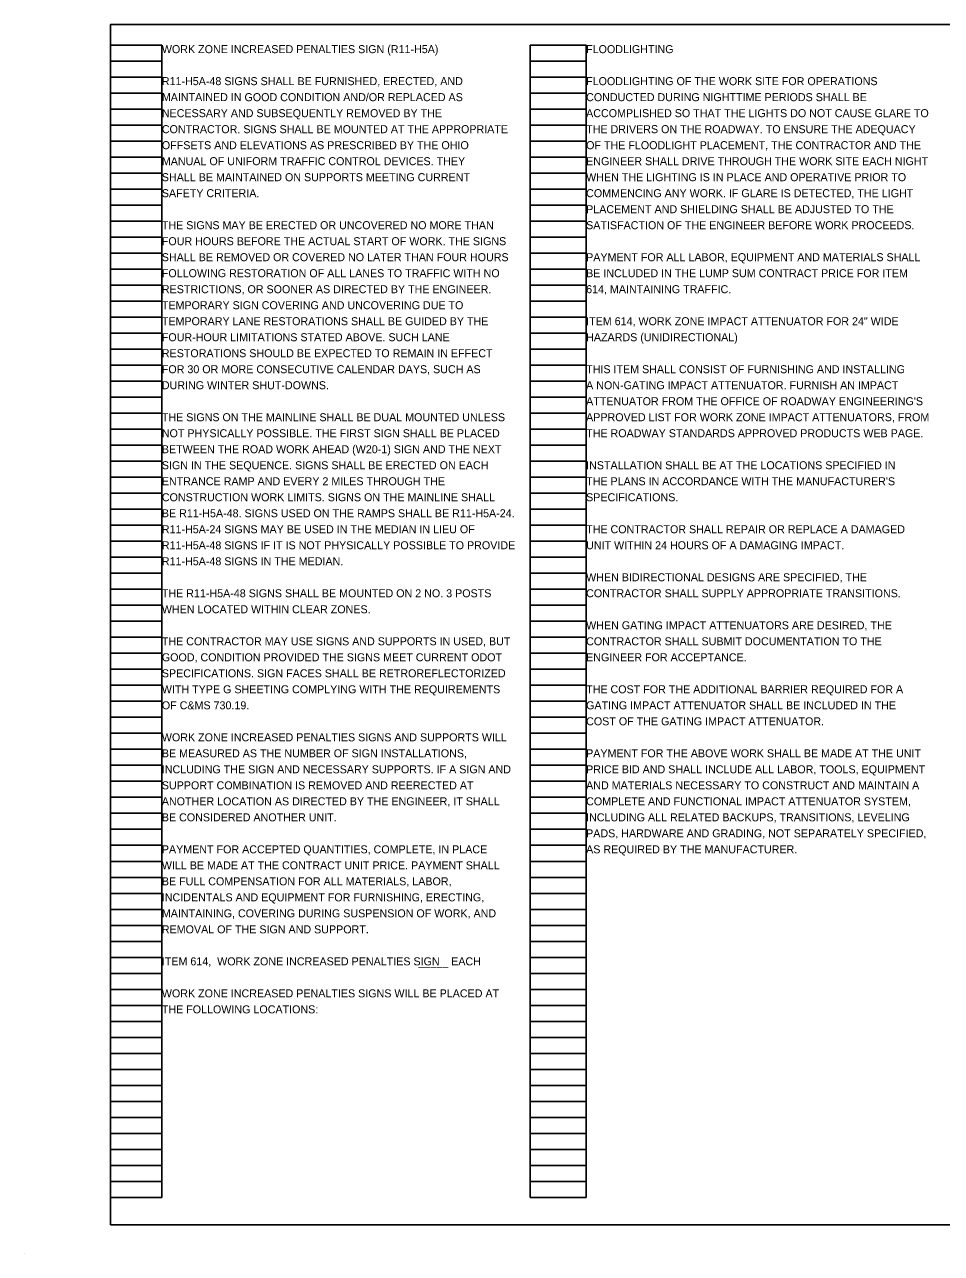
# Model space of a CAD drawing. Extents: x -34 to 2132911, y 0 to 658646.
# Drawn here: x 34 to 50.03, y 0 to 21.5 of the extents above; entities that cross this region are included whole.
import ezdxf

# ---------------------------------------------------------------- set-up
doc = ezdxf.new("R2010")
doc.units = 0
for name, color, linetype in [('SC_Scratch1', 7, 'Continuous'), ('SH_Data', 7, 'Continuous'), ('SH_Text', 7, 'Continuous')]:
    doc.layers.add(name, color=color, linetype=linetype)

msp = doc.modelspace()

# ---------------------------------------------------------------- linework, layer by layer
at = {"layer": 'SC_Scratch1'}
msp.add_lwpolyline([(35.5, 0.5), (66, 0.5), (66, 21.5), (35.5, 21.5)], close=True, dxfattribs=at)
at = {"layer": 'SH_Data'}
for p, q in [((35.5, 0.98), (35.5, 21.14)), ((35.5, 21.14), (36.4, 21.14)), ((36.4, 0.98), (36.4, 21.14)), ((42.84, 0.98), (42.84, 21.14)), ((42.84, 21.14), (43.82, 21.14)), ((43.82, 0.98), (43.82, 21.14)), ((35.5, 20.86), (36.4, 20.86)), ((42.84, 20.86), (43.82, 20.86)), ((35.5, 20.58), (36.4, 20.58)), ((42.84, 20.58), (43.82, 20.58)), ((35.5, 20.3), (36.4, 20.3)), ((42.84, 20.3), (43.82, 20.3)), ((35.5, 20.02), (36.4, 20.02)), ((42.84, 20.02), (43.82, 20.02)), ((35.5, 19.74), (36.4, 19.74)), ((42.84, 19.74), (43.82, 19.74)), ((35.5, 19.46), (36.4, 19.46)), ((42.84, 19.46), (43.82, 19.46)), ((35.5, 19.18), (36.4, 19.18)), ((42.84, 19.18), (43.82, 19.18)), ((35.5, 18.9), (36.4, 18.9)), ((42.84, 18.9), (43.82, 18.9)), ((35.5, 18.62), (36.4, 18.62)), ((42.84, 18.62), (43.82, 18.62)), ((35.5, 18.34), (36.4, 18.34)), ((42.84, 18.34), (43.82, 18.34)), ((35.5, 18.06), (36.4, 18.06)), ((42.84, 18.06), (43.82, 18.06)), ((35.5, 17.78), (36.4, 17.78)), ((42.84, 17.78), (43.82, 17.78)), ((35.5, 17.5), (36.4, 17.5)), ((42.84, 17.5), (43.82, 17.5)), ((35.5, 17.22), (36.4, 17.22)), ((42.84, 17.22), (43.82, 17.22)), ((35.5, 16.94), (36.4, 16.94)), ((42.84, 16.94), (43.82, 16.94)), ((35.5, 16.66), (36.4, 16.66)), ((42.84, 16.66), (43.82, 16.66)), ((35.5, 16.38), (36.4, 16.38)), ((42.84, 16.38), (43.82, 16.38)), ((35.5, 16.1), (36.4, 16.1)), ((42.84, 16.1), (43.82, 16.1)), ((35.5, 15.82), (36.4, 15.82)), ((42.84, 15.82), (43.82, 15.82)), ((35.5, 15.54), (36.4, 15.54)), ((42.84, 15.54), (43.82, 15.54)), ((35.5, 15.26), (36.4, 15.26)), ((42.84, 15.26), (43.82, 15.26)), ((35.5, 14.98), (36.4, 14.98)), ((42.84, 14.98), (43.82, 14.98)), ((35.5, 14.7), (36.4, 14.7)), ((42.84, 14.7), (43.82, 14.7)), ((35.5, 14.42), (36.4, 14.42)), ((42.84, 14.42), (43.82, 14.42)), ((35.5, 14.14), (36.4, 14.14)), ((42.84, 14.14), (43.82, 14.14)), ((35.5, 13.86), (36.4, 13.86)), ((42.84, 13.86), (43.82, 13.86)), ((35.5, 13.58), (36.4, 13.58)), ((42.84, 13.58), (43.82, 13.58)), ((35.5, 13.3), (36.4, 13.3)), ((42.84, 13.3), (43.82, 13.3)), ((35.5, 13.02), (36.4, 13.02)), ((42.84, 13.02), (43.82, 13.02)), ((35.5, 12.74), (36.4, 12.74)), ((42.84, 12.74), (43.82, 12.74)), ((35.5, 12.46), (36.4, 12.46)), ((42.84, 12.46), (43.82, 12.46)), ((35.5, 12.18), (36.4, 12.18)), ((42.84, 12.18), (43.82, 12.18)), ((35.5, 11.9), (36.4, 11.9)), ((42.84, 11.9), (43.82, 11.9)), ((35.5, 11.62), (36.4, 11.62)), ((42.84, 11.62), (43.82, 11.62)), ((35.5, 11.34), (36.4, 11.34)), ((42.84, 11.34), (43.82, 11.34)), ((35.5, 11.06), (36.4, 11.06)), ((42.84, 11.06), (43.82, 11.06)), ((35.5, 10.78), (36.4, 10.78)), ((42.84, 10.78), (43.82, 10.78)), ((35.5, 10.5), (36.4, 10.5)), ((42.84, 10.5), (43.82, 10.5)), ((35.5, 10.22), (36.4, 10.22)), ((42.84, 10.22), (43.82, 10.22)), ((35.5, 9.94), (36.4, 9.94)), ((42.84, 9.94), (43.82, 9.94)), ((35.5, 9.66), (36.4, 9.66)), ((42.84, 9.66), (43.82, 9.66)), ((35.5, 9.38), (36.4, 9.38)), ((42.84, 9.38), (43.82, 9.38)), ((35.5, 9.1), (36.4, 9.1)), ((42.84, 9.1), (43.82, 9.1)), ((35.5, 8.82), (36.4, 8.82)), ((42.84, 8.82), (43.82, 8.82)), ((35.5, 8.54), (36.4, 8.54)), ((42.84, 8.54), (43.82, 8.54)), ((35.5, 8.26), (36.4, 8.26)), ((42.84, 8.26), (43.82, 8.26)), ((35.5, 7.98), (36.4, 7.98)), ((42.84, 7.98), (43.82, 7.98)), ((35.5, 7.7), (36.4, 7.7)), ((42.84, 7.7), (43.82, 7.7)), ((35.5, 7.42), (36.4, 7.42)), ((42.84, 7.42), (43.82, 7.42)), ((35.5, 7.14), (36.4, 7.14)), ((42.84, 7.14), (43.82, 7.14)), ((35.5, 6.86), (36.4, 6.86)), ((42.84, 6.86), (43.82, 6.86)), ((35.5, 6.58), (36.4, 6.58)), ((42.84, 6.58), (43.82, 6.58)), ((35.5, 6.3), (36.4, 6.3)), ((42.84, 6.3), (43.82, 6.3)), ((35.5, 6.02), (36.4, 6.02)), ((42.84, 6.02), (43.82, 6.02)), ((35.5, 5.74), (36.4, 5.74)), ((42.84, 5.74), (43.82, 5.74)), ((35.5, 5.46), (36.4, 5.46)), ((42.84, 5.46), (43.82, 5.46)), ((35.5, 5.18), (36.4, 5.18)), ((42.84, 5.18), (43.82, 5.18)), ((35.5, 4.9), (36.4, 4.9)), ((42.84, 4.9), (43.82, 4.9)), ((35.5, 4.62), (36.4, 4.62)), ((42.84, 4.62), (43.82, 4.62)), ((35.5, 4.34), (36.4, 4.34)), ((42.84, 4.34), (43.82, 4.34)), ((35.5, 4.06), (36.4, 4.06)), ((42.84, 4.06), (43.82, 4.06)), ((35.5, 3.78), (36.4, 3.78)), ((42.84, 3.78), (43.82, 3.78)), ((35.5, 3.5), (36.4, 3.5)), ((42.84, 3.5), (43.82, 3.5)), ((35.5, 3.22), (36.4, 3.22)), ((42.84, 3.22), (43.82, 3.22)), ((35.5, 2.94), (36.4, 2.94)), ((42.84, 2.94), (43.82, 2.94)), ((35.5, 2.66), (36.4, 2.66)), ((42.84, 2.66), (43.82, 2.66)), ((35.5, 2.38), (36.4, 2.38)), ((42.84, 2.38), (43.82, 2.38)), ((35.5, 2.1), (36.4, 2.1)), ((42.84, 2.1), (43.82, 2.1)), ((35.5, 1.82), (36.4, 1.82)), ((42.84, 1.82), (43.82, 1.82)), ((35.5, 1.54), (36.4, 1.54)), ((42.84, 1.54), (43.82, 1.54)), ((35.5, 1.26), (36.4, 1.26)), ((42.84, 1.26), (43.82, 1.26)), ((35.5, 0.98), (36.4, 0.98)), ((42.84, 0.98), (43.82, 0.98)), ((34, 0), (34, 0))]:
    msp.add_line(p, q, dxfattribs=at)

# ---------------------------------------------------------------- texts
at = {"layer": 'SH_Text'}
for s, p in [('WORK ZONE INCREASED PENALTIES SIGN (R11-H5A)', (36.4, 21)), ('FLOODLIGHTING', (43.82, 21)), ('R11-H5A-48 SIGNS SHALL BE FURNISHED, ERECTED, AND', (36.4, 20.44)), ('FLOODLIGHTING OF THE WORK SITE FOR OPERATIONS', (43.82, 20.44)), ('MAINTAINED IN GOOD CONDITION AND/OR REPLACED AS', (36.4, 20.16)), ('CONDUCTED DURING NIGHTTIME PERIODS SHALL BE', (43.82, 20.16)), ('NECESSARY AND SUBSEQUENTLY REMOVED BY THE', (36.4, 19.88)), ('ACCOMPLISHED SO THAT THE LIGHTS DO NOT CAUSE GLARE TO', (43.82, 19.88)), ('CONTRACTOR. SIGNS SHALL BE MOUNTED AT THE APPROPRIATE', (36.4, 19.6)), ('THE DRIVERS ON THE ROADWAY. TO ENSURE THE ADEQUACY', (43.82, 19.6)), ('OFFSETS AND ELEVATIONS AS PRESCRIBED BY THE OHIO', (36.4, 19.32)), ('OF THE FLOODLIGHT PLACEMENT, THE CONTRACTOR AND THE', (43.82, 19.32)), ('MANUAL OF UNIFORM TRAFFIC CONTROL DEVICES. THEY', (36.4, 19.04)), ('ENGINEER SHALL DRIVE THROUGH THE WORK SITE EACH NIGHT', (43.82, 19.04)), ('SHALL BE MAINTAINED ON SUPPORTS MEETING CURRENT', (36.4, 18.76)), ('WHEN THE LIGHTING IS IN PLACE AND OPERATIVE PRIOR TO', (43.82, 18.76)), ('SAFETY CRITERIA.', (36.4, 18.48)), ('COMMENCING ANY WORK. IF GLARE IS DETECTED, THE LIGHT', (43.82, 18.48)), ('PLACEMENT AND SHIELDING SHALL BE ADJUSTED TO THE', (43.82, 18.2)), ('THE SIGNS MAY BE ERECTED OR UNCOVERED NO MORE THAN', (36.4, 17.92)), ('SATISFACTION OF THE ENGINEER BEFORE WORK PROCEEDS.', (43.82, 17.92)), ('FOUR HOURS BEFORE THE ACTUAL START OF WORK. THE SIGNS', (36.4, 17.64)), ('SHALL BE REMOVED OR COVERED NO LATER THAN FOUR HOURS', (36.4, 17.36)), ('PAYMENT FOR ALL LABOR, EQUIPMENT AND MATERIALS SHALL', (43.82, 17.36)), ('FOLLOWING RESTORATION OF ALL LANES TO TRAFFIC WITH NO', (36.4, 17.08)), ('BE INCLUDED IN THE LUMP SUM CONTRACT PRICE FOR ITEM', (43.82, 17.08)), ('RESTRICTIONS, OR SOONER AS DIRECTED BY THE ENGINEER.', (36.4, 16.8)), ('614, MAINTAINING TRAFFIC.', (43.82, 16.8)), ('TEMPORARY SIGN COVERING AND UNCOVERING DUE TO', (36.4, 16.52)), ('TEMPORARY LANE RESTORATIONS SHALL BE GUIDED BY THE', (36.4, 16.24)), ('ITEM 614, WORK ZONE IMPACT ATTENUATOR FOR 24" WIDE', (43.82, 16.24)), ('FOUR-HOUR LIMITATIONS STATED ABOVE. SUCH LANE', (36.4, 15.96)), ('HAZARDS (UNIDIRECTIONAL)', (43.82, 15.96)), ('RESTORATIONS SHOULD BE EXPECTED TO REMAIN IN EFFECT', (36.4, 15.68)), ('FOR 30 OR MORE CONSECUTIVE CALENDAR DAYS, SUCH AS', (36.4, 15.4)), ('THIS ITEM SHALL CONSIST OF FURNISHING AND INSTALLING', (43.82, 15.4)), ('DURING WINTER SHUT-DOWNS.', (36.4, 15.12)), ('A NON-GATING IMPACT ATTENUATOR. FURNISH AN IMPACT', (43.82, 15.12)), ("ATTENUATOR FROM THE OFFICE OF ROADWAY ENGINEERING'S", (43.82, 14.84)), ('THE SIGNS ON THE MAINLINE SHALL BE DUAL MOUNTED UNLESS', (36.4, 14.56)), ('APPROVED LIST FOR WORK ZONE IMPACT ATTENUATORS, FROM', (43.82, 14.56)), ('NOT PHYSICALLY POSSIBLE. THE FIRST SIGN SHALL BE PLACED', (36.4, 14.28)), ('THE ROADWAY STANDARDS APPROVED PRODUCTS WEB PAGE.', (43.82, 14.28)), ('BETWEEN THE ROAD WORK AHEAD (W20-1) SIGN AND THE NEXT', (36.4, 14)), ('SIGN IN THE SEQUENCE. SIGNS SHALL BE ERECTED ON EACH', (36.4, 13.72)), ('INSTALLATION SHALL BE AT THE LOCATIONS SPECIFIED IN', (43.82, 13.72)), ('ENTRANCE RAMP AND EVERY 2 MILES THROUGH THE', (36.4, 13.44)), ("THE PLANS IN ACCORDANCE WITH THE MANUFACTURER'S", (43.82, 13.44)), ('CONSTRUCTION WORK LIMITS. SIGNS ON THE MAINLINE SHALL', (36.4, 13.16)), ('SPECIFICATIONS.', (43.82, 13.16)), ('BE R11-H5A-48. SIGNS USED ON THE RAMPS SHALL BE R11-H5A-24.', (36.4, 12.88)), ('R11-H5A-24 SIGNS MAY BE USED IN THE MEDIAN IN LIEU OF', (36.4, 12.6)), ('THE CONTRACTOR SHALL REPAIR OR REPLACE A DAMAGED', (43.82, 12.6)), ('R11-H5A-48 SIGNS IF IT IS NOT PHYSICALLY POSSIBLE TO PROVIDE', (36.4, 12.32)), ('UNIT WITHIN 24 HOURS OF A DAMAGING IMPACT.', (43.82, 12.32)), ('R11-H5A-48 SIGNS IN THE MEDIAN.', (36.4, 12.04)), ('WHEN BIDIRECTIONAL DESIGNS ARE SPECIFIED, THE', (43.82, 11.76)), ('THE R11-H5A-48 SIGNS SHALL BE MOUNTED ON 2 NO. 3 POSTS', (36.4, 11.48)), ('CONTRACTOR SHALL SUPPLY APPROPRIATE TRANSITIONS.', (43.82, 11.48)), ('WHEN LOCATED WITHIN CLEAR ZONES.', (36.4, 11.2)), ('WHEN GATING IMPACT ATTENUATORS ARE DESIRED, THE', (43.82, 10.92)), ('THE CONTRACTOR MAY USE SIGNS AND SUPPORTS IN USED, BUT', (36.4, 10.64)), ('CONTRACTOR SHALL SUBMIT DOCUMENTATION TO THE', (43.82, 10.64)), ('GOOD, CONDITION PROVIDED THE SIGNS MEET CURRENT ODOT', (36.4, 10.36)), ('ENGINEER FOR ACCEPTANCE.', (43.82, 10.36)), ('SPECIFICATIONS. SIGN FACES SHALL BE RETROREFLECTORIZED', (36.4, 10.08)), ('WITH TYPE G SHEETING COMPLYING WITH THE REQUIREMENTS', (36.4, 9.8)), ('THE COST FOR THE ADDITIONAL BARRIER REQUIRED FOR A', (43.82, 9.8)), ('OF C&MS 730.19.', (36.4, 9.52)), ('GATING IMPACT ATTENUATOR SHALL BE INCLUDED IN THE', (43.82, 9.52)), ('COST OF THE GATING IMPACT ATTENUATOR.', (43.82, 9.24)), ('WORK ZONE INCREASED PENALTIES SIGNS AND SUPPORTS WILL', (36.4, 8.96)), ('BE MEASURED AS THE NUMBER OF SIGN INSTALLATIONS,', (36.4, 8.68)), ('PAYMENT FOR THE ABOVE WORK SHALL BE MADE AT THE UNIT', (43.82, 8.68)), ('INCLUDING THE SIGN AND NECESSARY SUPPORTS. IF A SIGN AND', (36.4, 8.4)), ('PRICE BID AND SHALL INCLUDE ALL LABOR, TOOLS, EQUIPMENT', (43.82, 8.4)), ('SUPPORT COMBINATION IS REMOVED AND REERECTED AT', (36.4, 8.12)), ('AND MATERIALS NECESSARY TO CONSTRUCT AND MAINTAIN A', (43.82, 8.12)), ('ANOTHER LOCATION AS DIRECTED BY THE ENGINEER, IT SHALL', (36.4, 7.84)), ('COMPLETE AND FUNCTIONAL IMPACT ATTENUATOR SYSTEM,', (43.82, 7.84)), ('BE CONSIDERED ANOTHER UNIT.', (36.4, 7.56)), ('INCLUDING ALL RELATED BACKUPS, TRANSITIONS, LEVELING', (43.82, 7.56)), ('PADS, HARDWARE AND GRADING, NOT SEPARATELY SPECIFIED,', (43.82, 7.28)), ('PAYMENT FOR ACCEPTED QUANTITIES, COMPLETE, IN PLACE', (36.4, 7)), ('AS REQUIRED BY THE MANUFACTURER.', (43.82, 7)), ('WILL BE MADE AT THE CONTRACT UNIT PRICE. PAYMENT SHALL', (36.4, 6.72)), ('BE FULL COMPENSATION FOR ALL MATERIALS, LABOR,', (36.4, 6.44)), ('INCIDENTALS AND EQUIPMENT FOR FURNISHING, ERECTING,', (36.4, 6.16)), ('MAINTAINING, COVERING DURING SUSPENSION OF WORK, AND', (36.4, 5.88)), ('REMOVAL OF THE SIGN AND SUPPORT.', (36.4, 5.6)), ('ITEM 614, ', (36.4, 5.04)), ('WORK ZONE INCREASED PENALTIES SIGN ', (37.368, 5.04)), ('  _____ EACH', (40.783, 5.04)), ('WORK ZONE INCREASED PENALTIES SIGNS WILL BE PLACED AT', (36.4, 4.48)), ('THE FOLLOWING LOCATIONS:', (36.4, 4.2))]:
    msp.add_text(s, height=0.14, dxfattribs=at).set_placement(p)

doc.saveas('drawing.dxf')
